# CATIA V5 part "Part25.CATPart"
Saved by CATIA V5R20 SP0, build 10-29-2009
Part number: FA 084700-2 comprimido
Revision: ANY
Definition: UNKNOWN
Nomenclature: FA 084700-2 comprimido
Source: Unknown
Bounding box of the stored display mesh (mm): x -2.45 to 2.45, y 0 to 4.72, z -2.45 to 2.45
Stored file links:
  C:\Users\Utente\Desktop\IO LAVORO\3D X SITO CF\CUMSA\3D files FA\FA 1057SF\Part25.CATPart

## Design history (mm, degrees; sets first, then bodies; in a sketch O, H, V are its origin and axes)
Body1 "Cortar-Extruir1" (main body)
  Solid1: solid without history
